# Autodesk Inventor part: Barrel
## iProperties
Created: 2008-09
Part Number: Barrel
Document SubType Name: Modeling
Designer: the-dude
Density: 1 g/cm^3
Author: the-dude
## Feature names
1. MMC# 8585K22 [Revolution]
2. Revolution3
